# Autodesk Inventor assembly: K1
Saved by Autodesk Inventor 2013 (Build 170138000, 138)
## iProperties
Created: 2021-02
Part Number: K1
Document SubType Name: Assembly
Designer: Fede
Author: Fede
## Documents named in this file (2)
- C:\0000 FEDE\16GB\0000 INTERIOR\DE_TMP_BAS\BAS_DTON - demora conexion al energizar\pcb\BOR\turn on\Imported Components\BAS_DTON\K1.iam
- C:\0000 FEDE\16GB\0000 INTERIOR\DE_TMP_BAS\BAS_DTON - demora conexion al energizar\pcb\BOR\turn on\Imported Components\BAS_DTON\relay.iam
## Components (1 placed, 1 different names)
1. relay:1 [sub-assembly]
